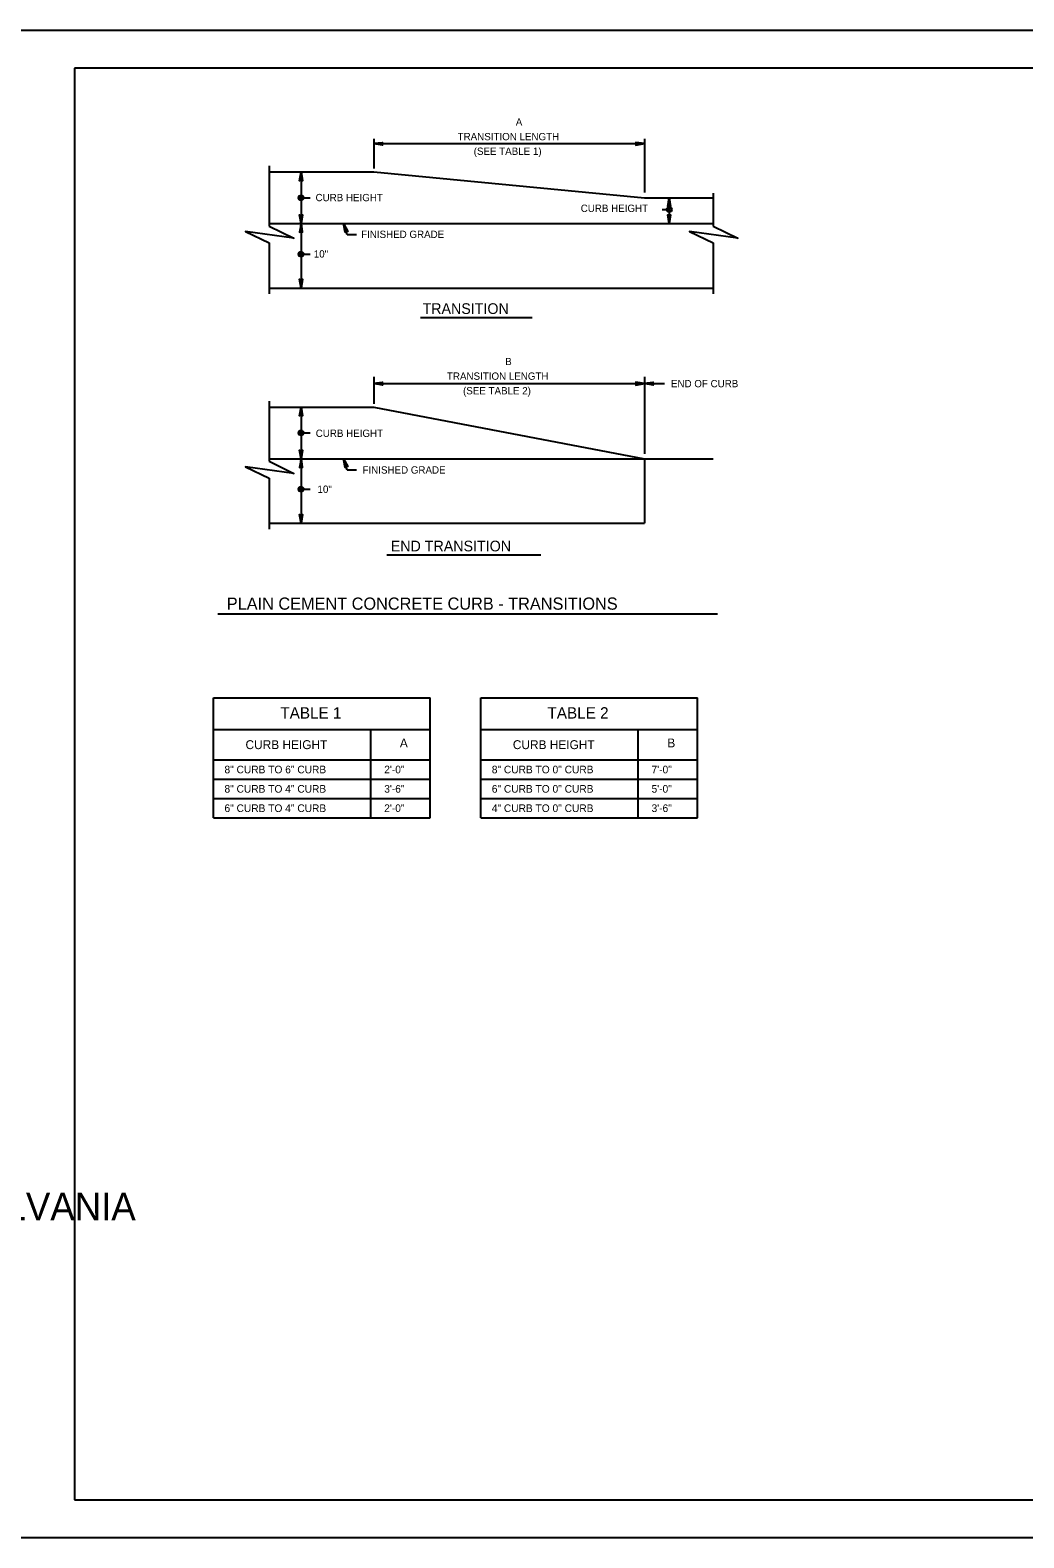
# Model space of a CAD drawing. Extents: x 2092490 to 2102560, y 980575 to 982524.
# Drawn here: x 2099664 to 2100949, y 980575 to 982524 of the extents above; entities that cross this region are included whole.
import ezdxf

# ---------------------------------------------------------------- set-up
doc = ezdxf.new("R2010")
doc.units = 0
for name, color, linetype in [('1', 7, 'Continuous'), ('2', 7, 'Continuous'), ('3', 7, 'Continuous'), ('PLT-BNDY', 7, 'Continuous')]:
    doc.layers.add(name, color=color, linetype=linetype)

msp = doc.modelspace()

# ---------------------------------------------------------------- linework, layer by layer
at = {"layer": '1'}
for p, q in [((2102300, 982474.5), (2099721.2, 982474.5)), ((2099721.2, 982474.5), (2099721.2, 980624.1)), ((2099901.3, 981505.5), (2099901.3, 981660.5)), ((2099901.3, 981660.5), (2100181.2, 981660.5)), ((2100181.2, 981505.5), (2100181.2, 981660.5)), ((2100247, 981505.5), (2100247, 981660.5)), ((2100247, 981660.5), (2100526.9, 981660.5)), ((2100526.9, 981505.5), (2100526.9, 981660.5)), ((2099901.3, 981619.8), (2100181.2, 981619.8)), ((2100104.7, 981505.5), (2100104.7, 981619.8)), ((2100247, 981619.8), (2100526.9, 981619.8)), ((2100450.4, 981505.5), (2100450.4, 981619.8)), ((2099901.3, 981580.5), (2100181.2, 981580.5)), ((2100247, 981580.5), (2100526.9, 981580.5)), ((2099901.3, 981555.5), (2100181.2, 981555.5)), ((2100247, 981555.5), (2100526.9, 981555.5)), ((2099901.3, 981530.5), (2100181.2, 981530.5)), ((2100247, 981530.5), (2100526.9, 981530.5)), ((2099901.3, 981505.5), (2100181.2, 981505.5)), ((2100247, 981505.5), (2100526.9, 981505.5)), ((2099721.2, 980624.1), (2102300, 980624.1))]:
    msp.add_line(p, q, dxfattribs=at)
at = {"layer": '2'}
for p, q in [((2100108.6, 982383.3), (2100108.6, 982344.8)), ((2100458.6, 982383.3), (2100458.6, 982313.7)), ((2099973.1, 982340.4), (2100108.6, 982340.4)), ((2100014.3, 982340.4), (2100014.3, 982190.4)), ((2100108.6, 982340.4), (2100458.6, 982307.1)), ((2100458.6, 982307.1), (2100547.3, 982307.1)), ((2100490.4, 982307.1), (2100490.4, 982273.7)), ((2099973.1, 982273.7), (2100547.3, 982273.7)), ((2099973.1, 982190.4), (2100547.3, 982190.4)), ((2100108.6, 982075.4), (2100108.6, 982040.8)), ((2100458.6, 982075.4), (2100458.6, 981976)), ((2099973.1, 982036.4), (2100108.6, 982036.4)), ((2100014.3, 982036.4), (2100014.3, 981886.4)), ((2100108.6, 982036.4), (2100458.6, 981969.7)), ((2099973.1, 981969.7), (2100547.3, 981969.7)), ((2100458.6, 981969.7), (2100458.6, 981886.4)), ((2099973.1, 981886.4), (2100458.6, 981886.4))]:
    msp.add_line(p, q, dxfattribs=at)
at = {"layer": '3'}
for p, q in [((2100108.6, 982377), (2100458.6, 982377)), ((2099973.1, 982348.2), (2099973.1, 982270.4)), ((2100014.3, 982307.1), (2100026.3, 982307.1)), ((2100490.4, 982307.1), (2100502.4, 982307.1)), ((2100547.3, 982313.2), (2100547.3, 982270.4)), ((2100481.1, 982292), (2100490.4, 982292)), ((2100074, 982259.5), (2100069.4, 982273.7)), ((2099973.1, 982248.8), (2099973.1, 982182.7)), ((2100074, 982259.5), (2100086, 982259.5)), ((2100547.3, 982248.8), (2100547.3, 982182.7)), ((2100014.3, 982234.1), (2100026.3, 982234.1)), ((2100169, 982152.5), (2100313.2, 982152.5)), ((2100108.6, 982066.9), (2100484.4, 982066.9)), ((2099973.1, 982044.2), (2099973.1, 981966.5)), ((2100014.3, 982003.1), (2100026.3, 982003.1)), ((2100074, 981955.5), (2100069.4, 981969.7)), ((2100074, 981955.5), (2100086, 981955.5)), ((2099973.1, 981944.8), (2099973.1, 981878.7)), ((2100014.3, 981930.2), (2100026.3, 981930.2)), ((2100125.1, 981845.6), (2100324.4, 981845.6)), ((2099906.8, 981769.4), (2100552.8, 981769.4))]:
    msp.add_line(p, q, dxfattribs=at)
for points in [[(2100119.3, 982375.6), (2100118.9, 982376.4), (2100108.6, 982377), (2100119.3, 982375.6), (2100119.8, 982375.1), (2100108.6, 982377), (2100118.9, 982377.5), (2100119.3, 982378.2), (2100108.6, 982377), (2100119.8, 982378.7), (2100119.3, 982378.2)], [(2100447.8, 982375.6), (2100448.2, 982376.4), (2100458.6, 982377), (2100447.8, 982375.6), (2100447.3, 982375.1), (2100458.6, 982377), (2100448.3, 982377.5), (2100447.9, 982378.2), (2100458.6, 982377), (2100447.3, 982378.7), (2100447.9, 982378.2)], [(2100013, 982329.7), (2100013.8, 982330.1), (2100014.3, 982340.4), (2100013, 982329.7), (2100012.5, 982329.1), (2100014.3, 982340.4), (2100014.8, 982330.1), (2100015.6, 982329.7), (2100014.3, 982340.4), (2100016.1, 982329.1), (2100015.6, 982329.7)], [(2100489, 982296.3), (2100489.8, 982296.7), (2100490.4, 982307.1), (2100489, 982296.3), (2100488.6, 982295.8), (2100490.4, 982307.1), (2100490.9, 982296.7), (2100491.7, 982296.4), (2100490.4, 982307.1), (2100492.2, 982295.8), (2100491.7, 982296.4)], [(2100015.7, 982284.5), (2100014.9, 982284.1), (2100014.3, 982273.7), (2100015.7, 982284.5), (2100016.1, 982285), (2100014.3, 982273.7), (2100013.8, 982284), (2100013, 982284.4), (2100014.3, 982273.7), (2100012.5, 982285), (2100013, 982284.4)], [(2100491.7, 982284.5), (2100490.9, 982284.1), (2100490.4, 982273.7), (2100491.7, 982284.5), (2100492.2, 982285), (2100490.4, 982273.7), (2100489.9, 982284), (2100489.1, 982284.4), (2100490.4, 982273.7), (2100488.6, 982285), (2100489.1, 982284.4)], [(2099973.1, 982270.4), (2100005, 982254.8), (2099942.6, 982263.3), (2099973.1, 982248.8)], [(2100015.7, 982263), (2100014.9, 982263.4), (2100014.3, 982273.7), (2100015.7, 982263), (2100016.1, 982262.5), (2100014.3, 982273.7), (2100013.8, 982263.4), (2100013, 982263), (2100014.3, 982273.7), (2100012.5, 982262.5), (2100013, 982263)], [(2100071.5, 982263.1), (2100072.2, 982263.8), (2100069.4, 982273.7), (2100071.5, 982263.1), (2100071.3, 982262.5), (2100069.4, 982273.7), (2100073.2, 982264.1), (2100074, 982264), (2100069.4, 982273.7), (2100074.7, 982263.6), (2100074, 982264)], [(2100547.3, 982270.4), (2100579.2, 982254.8), (2100516.8, 982263.3), (2100547.3, 982248.8)], [(2100015.7, 982201.1), (2100014.9, 982200.7), (2100014.3, 982190.4), (2100015.7, 982201.1), (2100016.1, 982201.7), (2100014.3, 982190.4), (2100013.8, 982200.7), (2100013, 982201.1), (2100014.3, 982190.4), (2100012.5, 982201.7), (2100013, 982201.1)], [(2100119.3, 982065.5), (2100118.9, 982066.3), (2100108.6, 982066.9), (2100119.3, 982065.5), (2100119.8, 982065), (2100108.6, 982066.9), (2100118.9, 982067.4), (2100119.3, 982068.1), (2100108.6, 982066.9), (2100119.8, 982068.7), (2100119.3, 982068.1)], [(2100447.8, 982065.5), (2100448.2, 982066.3), (2100458.6, 982066.9), (2100447.8, 982065.5), (2100447.3, 982065), (2100458.6, 982066.9), (2100448.3, 982067.4), (2100447.9, 982068.1), (2100458.6, 982066.9), (2100447.3, 982068.7), (2100447.9, 982068.1)], [(2100469.3, 982065.5), (2100468.9, 982066.3), (2100458.6, 982066.9), (2100469.3, 982065.5), (2100469.8, 982065), (2100458.6, 982066.9), (2100468.9, 982067.4), (2100469.3, 982068.1), (2100458.6, 982066.9), (2100469.8, 982068.7), (2100469.3, 982068.1)], [(2100013, 982025.7), (2100013.8, 982026.1), (2100014.3, 982036.4), (2100013, 982025.7), (2100012.5, 982025.1), (2100014.3, 982036.4), (2100014.8, 982026.1), (2100015.6, 982025.7), (2100014.3, 982036.4), (2100016.1, 982025.1), (2100015.6, 982025.7)], [(2100015.7, 981980.5), (2100014.9, 981980.1), (2100014.3, 981969.7), (2100015.7, 981980.5), (2100016.1, 981981), (2100014.3, 981969.7), (2100013.8, 981980.1), (2100013, 981980.4), (2100014.3, 981969.7), (2100012.5, 981981), (2100013, 981980.4)], [(2099973.1, 981966.5), (2100005, 981950.8), (2099942.6, 981959.3), (2099973.1, 981944.8)], [(2100015.7, 981959), (2100014.9, 981959.4), (2100014.3, 981969.7), (2100015.7, 981959), (2100016.1, 981958.5), (2100014.3, 981969.7), (2100013.8, 981959.4), (2100013, 981959), (2100014.3, 981969.7), (2100012.5, 981958.5), (2100013, 981959)], [(2100071.5, 981959.1), (2100072.2, 981959.8), (2100069.4, 981969.7), (2100071.5, 981959.1), (2100071.3, 981958.5), (2100069.4, 981969.7), (2100073.2, 981960.1), (2100074, 981960), (2100069.4, 981969.7), (2100074.7, 981959.6), (2100074, 981960)], [(2100015.7, 981897.1), (2100014.9, 981896.7), (2100014.3, 981886.4), (2100015.7, 981897.1), (2100016.1, 981897.7), (2100014.3, 981886.4), (2100013.8, 981896.7), (2100013, 981897.1), (2100014.3, 981886.4), (2100012.5, 981897.7), (2100013, 981897.1)]]:
    msp.add_lwpolyline(points, dxfattribs=at)
for centre, radius in [((2100014.3, 982307.1), 3.28), ((2100014.3, 982307.1), 1.64), ((2100490.5, 982291.7), 3.28), ((2100490.5, 982291.7), 1.64), ((2100014.3, 982234.1), 3.28), ((2100014.3, 982234.1), 1.64), ((2100014.3, 982003.1), 3.28), ((2100014.3, 982003.1), 1.64), ((2100014.3, 981930.2), 3.28), ((2100014.3, 981930.2), 1.64)]:
    msp.add_circle(centre, radius, dxfattribs=at)
at = {"layer": 'PLT-BNDY'}
msp.add_lwpolyline([(2099593.3, 982523.7), (2102352.5, 982523.7), (2102352.5, 980574.9), (2099593.3, 980574.9)], close=True, dxfattribs=at)

# ---------------------------------------------------------------- texts
at = {"layer": '1'}
for s, height, p in [('TABLE 1', 14.76, (2099987.6, 981633.8)), ('TABLE 2', 14.76, (2100333, 981633.8)), ('CURB HEIGHT', 11.483, (2099942.5, 981594.4)), ('A', 11.5, (2100142.1, 981596.6)), ('CURB HEIGHT', 11.483, (2100288.2, 981594.4)), ('B', 11.5, (2100488, 981596.6)), ('8" CURB TO 6" CURB', 9.843, (2099915.3, 981563.1)), ('2\'-0"', 9.84, (2100121.9, 981563.1)), ('8" CURB TO 0" CURB', 9.843, (2100261, 981563.1)), ('7\'-0"', 9.84, (2100467.6, 981563.1)), ('8" CURB TO 4" CURB', 9.843, (2099915.3, 981538.1)), ('3\'-6"', 9.84, (2100121.9, 981538.1)), ('6" CURB TO 0" CURB', 9.843, (2100261, 981538.1)), ('5\'-0"', 9.84, (2100467.6, 981538.1)), ('6" CURB TO 4" CURB', 9.843, (2099915.3, 981513.1)), ('2\'-0"', 9.84, (2100121.9, 981513.1)), ('4" CURB TO 0" CURB', 9.843, (2100261, 981513.1)), ('3\'-6"', 9.84, (2100467.6, 981513.1)), ('COMMONWEALTH OF PENNSYLVANIA', 35.379, (2098927.8, 980985.5))]:
    msp.add_text(s, height=height, dxfattribs=at).set_placement(p)
at = {"layer": '3'}
for s, height, p in [('A', 9.45, (2100292, 982400.3)), ('TRANSITION LENGTH', 9.449, (2100216.8, 982381.4)), ('(SEE TABLE 1)', 9.449, (2100237.6, 982362.5)), ('CURB HEIGHT', 9.449, (2100033.1, 982302.6)), ('CURB HEIGHT', 9.449, (2100376, 982288.7)), ('FINISHED GRADE', 9.449, (2100092, 982255.1)), ('10"', 9.45, (2100030.8, 982229.8)), ('TRANSITION', 13.78, (2100171.4, 982156.9)), ('B', 9.45, (2100278.3, 982090.7)), ('TRANSITION LENGTH', 9.449, (2100203, 982071.8)), ('END OF CURB', 9.449, (2100492.7, 982062.1)), ('(SEE TABLE 2)', 9.449, (2100223.8, 982052.9)), ('CURB HEIGHT', 9.449, (2100033.3, 981997.9)), ('FINISHED GRADE', 9.449, (2100093.8, 981950.5)), ('10"', 9.45, (2100035.6, 981925.6)), ('END TRANSITION', 13.78, (2100130.3, 981850)), ('PLAIN CEMENT CONCRETE CURB - TRANSITIONS', 15.748, (2099918.3, 981774.6))]:
    msp.add_text(s, height=height, dxfattribs=at).set_placement(p)

doc.saveas('drawing.dxf')
